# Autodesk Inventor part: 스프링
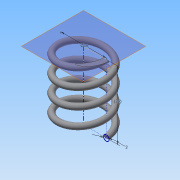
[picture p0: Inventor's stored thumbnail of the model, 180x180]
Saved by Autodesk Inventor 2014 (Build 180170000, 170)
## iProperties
Created: 2015-04
Part Number: 스프링
Material: Generic
Document SubType Name: Modeling
Designer: Administrator
Density: 1 g/cm^3
Appearance: Default
Mass: 0.60807 g
Surface Area: 12.5277 cm^2
Volume: 0.60807 cm^3
Author: Administrator
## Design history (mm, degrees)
sketch "스케치2"
  geometry: L1 (0, 0)-(8, 0); L2 (8, 0)-(8, 11.5); L3 (8, 11.5)-(0, 11.5); L4 (0, 11.5)-(0, 0); C1 r 1 at (8, 0)
  constraints: 8 end point, 2 parallel, 1 centre point, 1 coincident, 1 horizontal, 1 perpendicular
  dimensions: "d0" = 16 diameter of L2 L4; "d1" = 11.50049 distance between parallel lines of L3 L1 (derived); "d2" = 2 diameter of C1
feature "코일1" pitch "d3" = 10; turns "d5" = 4; dims "d4" = 11.50049 (= d1), "d6" = 0, angle "d7" = 90 deg, angle "d8" = 90 deg, "d9" = 0, "d10" = 0
sketch "스케치3"
  geometry: L1 (-9, 0)-(-7, 0) reference; 1 further point
  constraints: 1 horizontal alignment
extrude "돌출1" cut sketch "스케치3" stored distance "d11" = 10; taper "d12" = 0 deg
node "작업 평면1"
sketch "스케치4"
  geometry: L1 (9, 0)-(7, 0) reference; 1 further point
  constraints: 1 horizontal alignment
extrude "돌출2" cut sketch "스케치4" stored distance "d13" = 10; taper "d14" = 0 deg
node "솔리드1"
node "절단 모서리 투영1"
node "절단 모서리 투영2"
